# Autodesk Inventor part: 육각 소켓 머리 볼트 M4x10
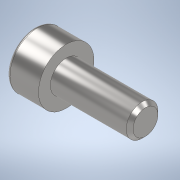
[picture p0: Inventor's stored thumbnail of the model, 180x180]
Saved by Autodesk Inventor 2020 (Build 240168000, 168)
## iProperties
Created: 2024-05
Part Number: 육각 소켓 머리 볼트 M4x10
Material: 강철, 연강
Description: 6각머리 태핑 나사
Document SubType Name: Modeling
Designer: oem
Density: 7.85 g/cm^3
Appearance: 기본값
Author: jhkim
Sending System: Autodesk Inventor 2025
Preprocessor: ST-DEVELOPER v20
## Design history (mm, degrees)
feature "Solid1"
node "솔리드1"
